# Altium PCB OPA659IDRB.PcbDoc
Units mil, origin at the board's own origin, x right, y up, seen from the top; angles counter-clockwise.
Board outline 4500 x 3000 mil, 4 copper layers (Top Layer, MidLayer1, MidLayer2, Bottom Layer); 16 components, 11 nets, 73 pads, 38 vias.
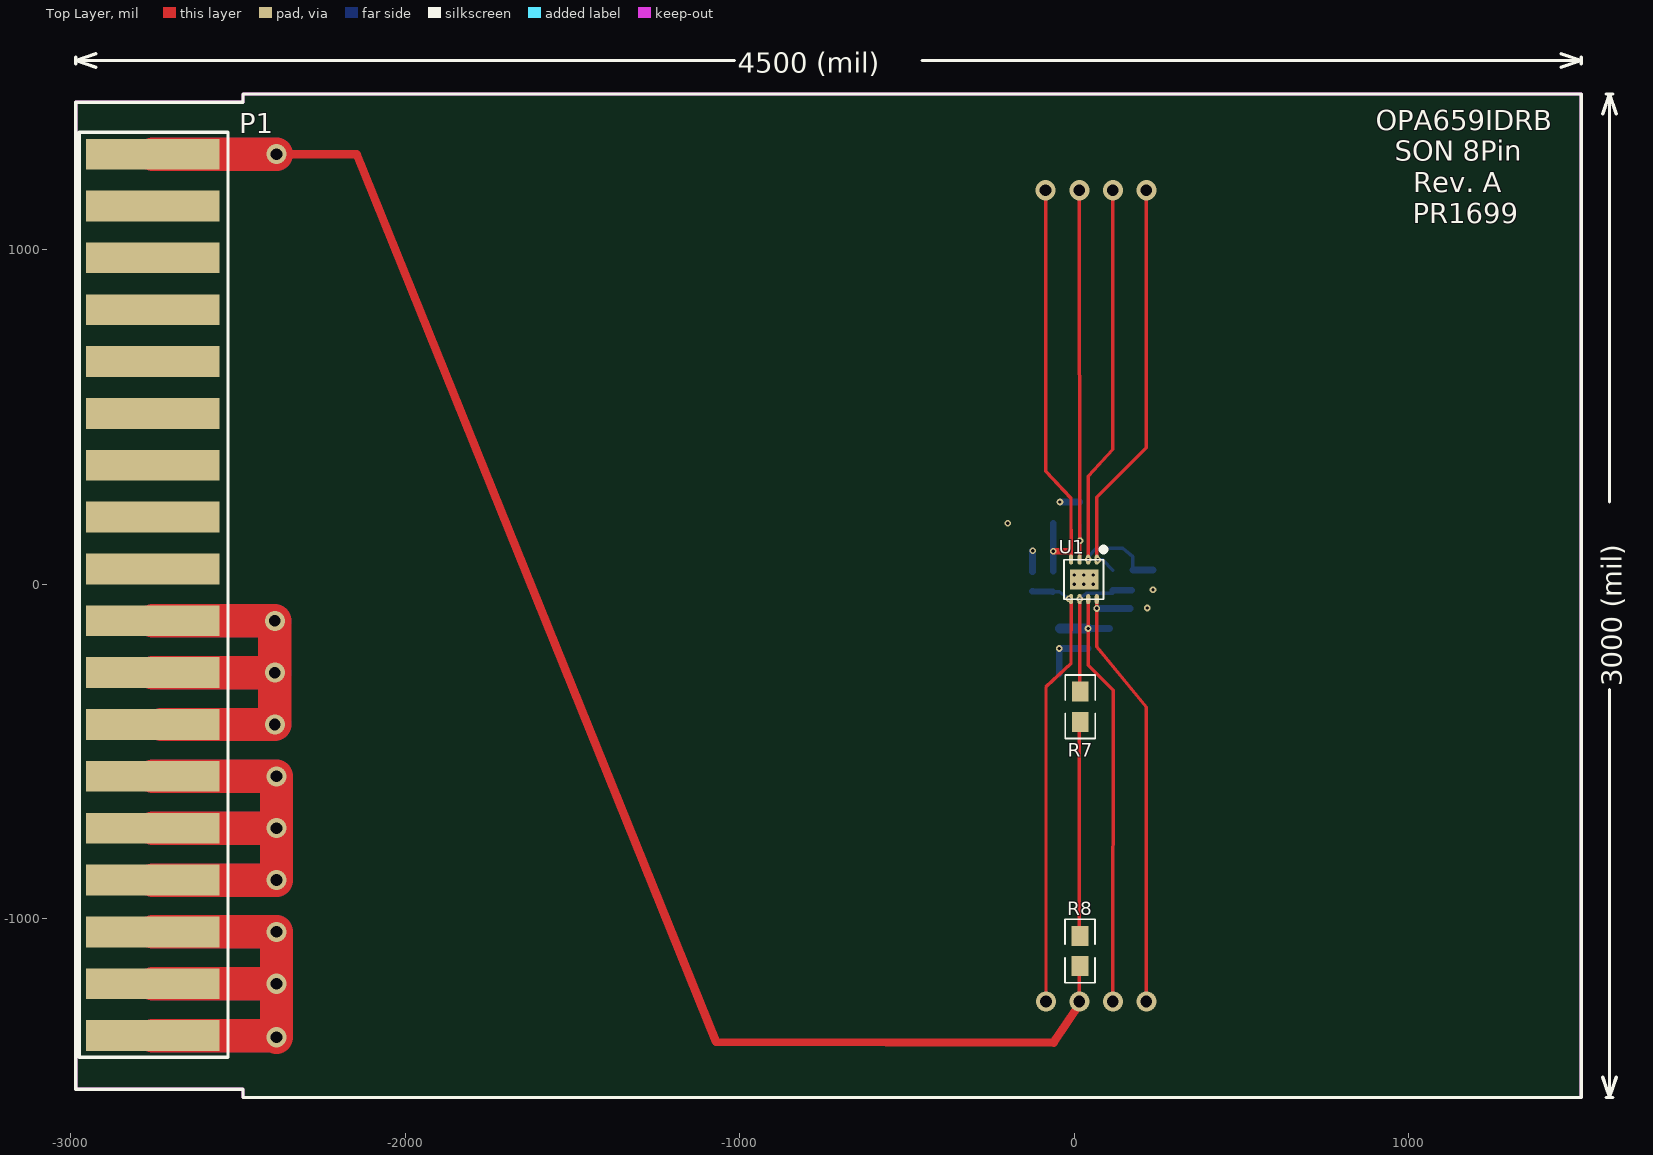
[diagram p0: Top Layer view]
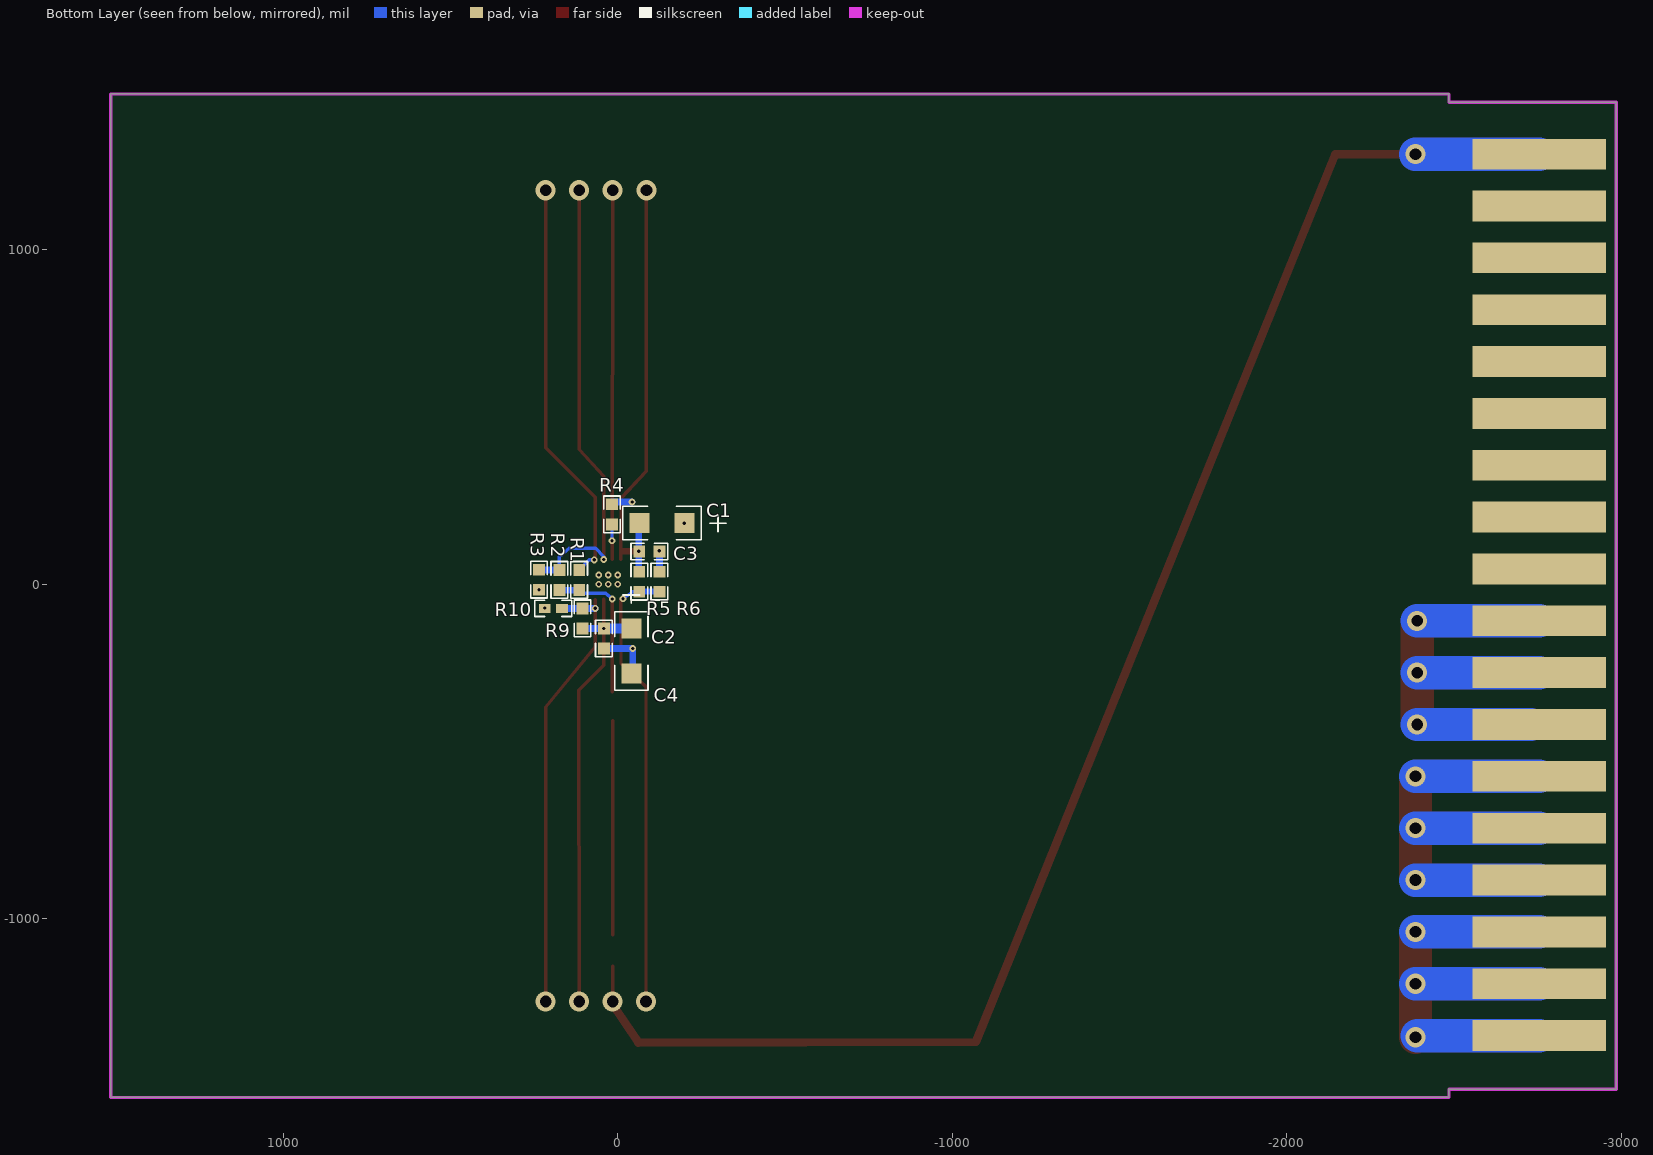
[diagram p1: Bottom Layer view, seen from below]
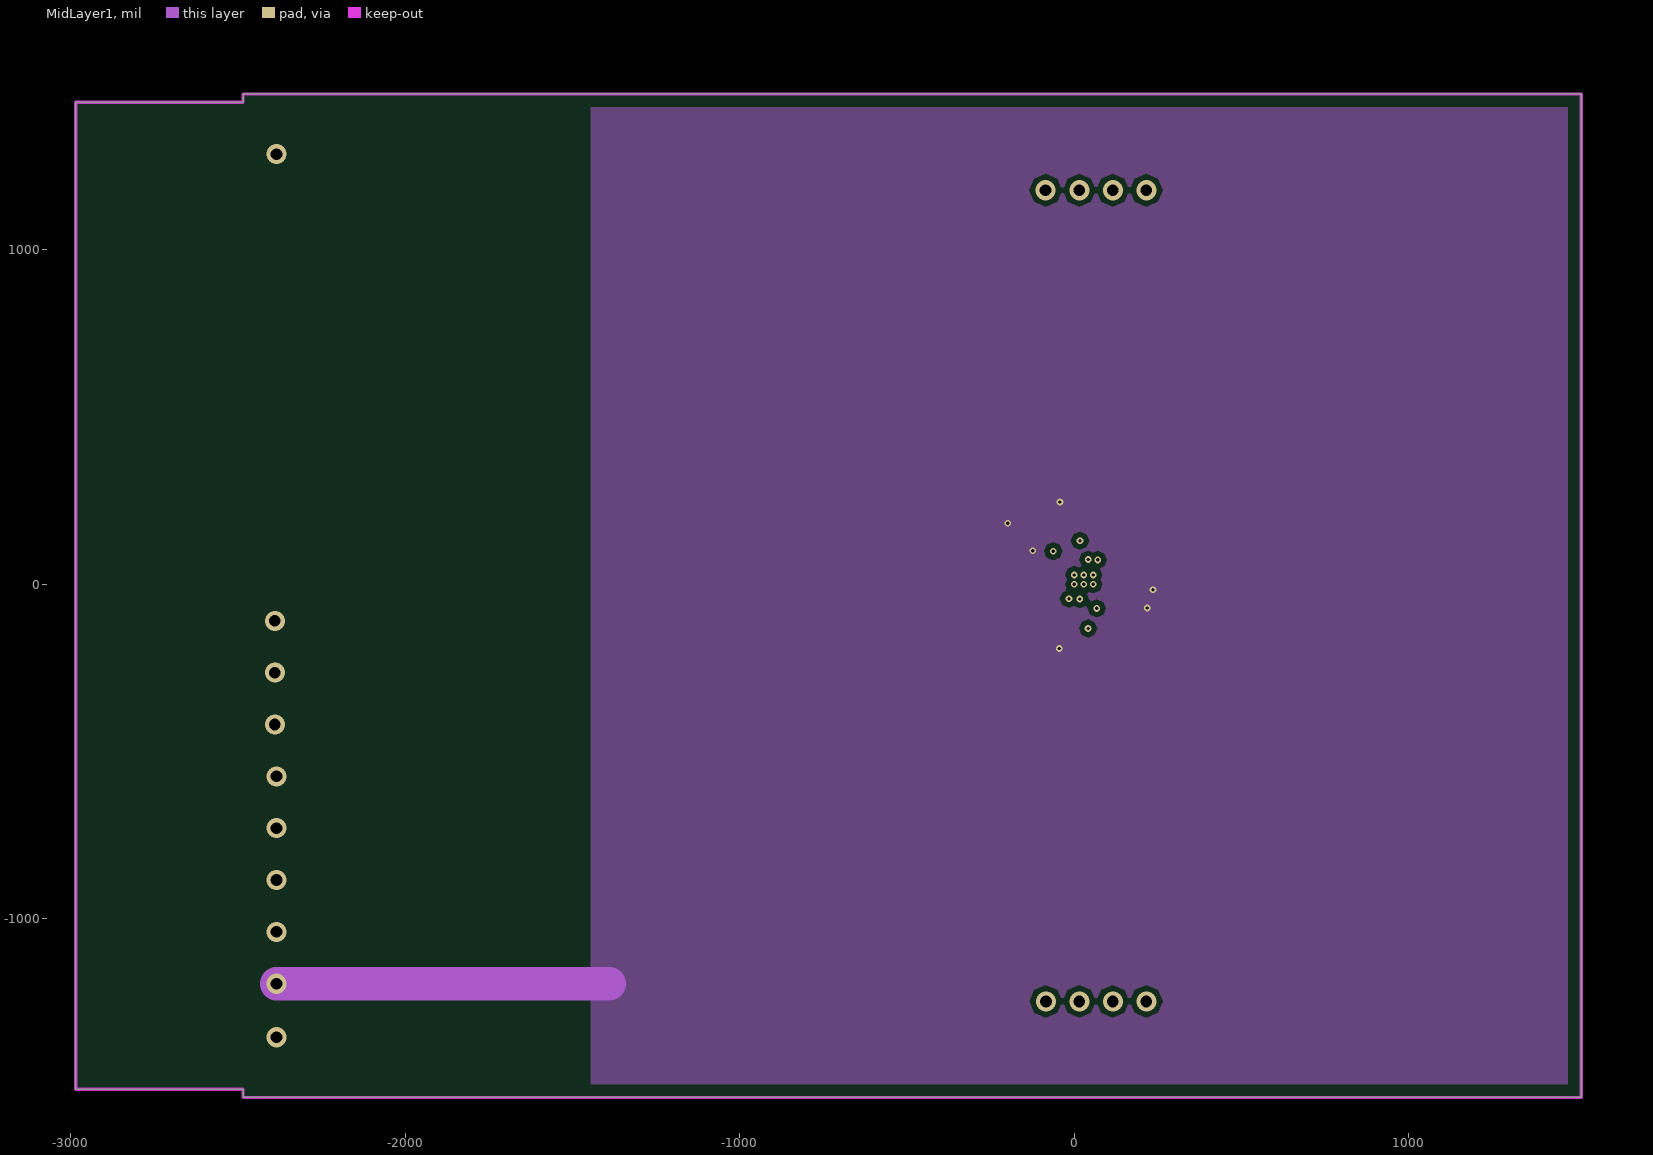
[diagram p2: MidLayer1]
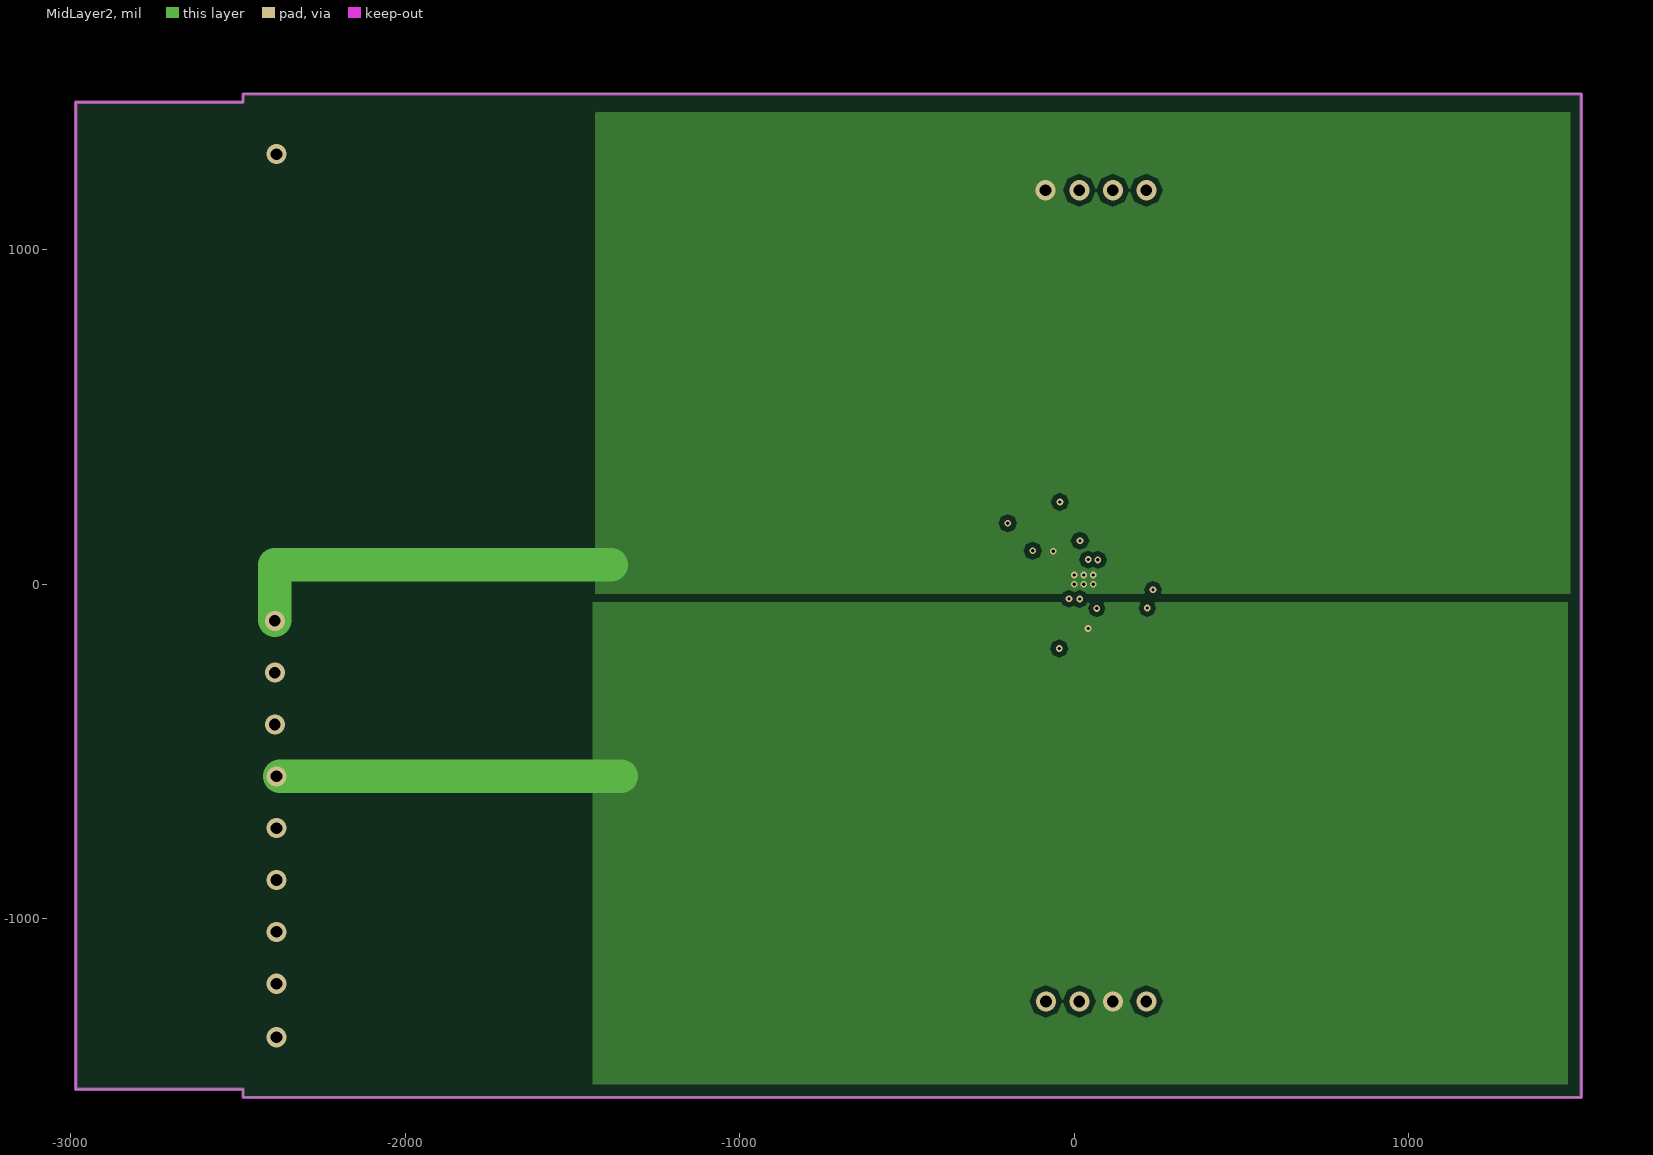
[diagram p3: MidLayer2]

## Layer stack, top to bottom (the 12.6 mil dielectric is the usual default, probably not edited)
Top Layer: signal copper 1.4
Dielectric: prepreg 12.6, FR-4, Dk 4.8
MidLayer1: signal copper 1.4
Dielectric: core 12.6, FR-4, Dk 4.8
MidLayer2: signal copper 1.4
Dielectric: prepreg 12.6, FR-4, Dk 4.8
Bottom Layer: signal copper 1.4

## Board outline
-2985.2,1441 -2485.2,1441 -2485.2,1466 1514.8,1466 1514.8,-1534 -2485.2,-1534 -2485.2,-1509 -2985.2,-1509

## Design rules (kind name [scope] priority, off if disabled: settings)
Clearance [All] p1: gap=5
ComponentClearance [All] p1: gap=10 collisioncheckmode=0 verticalgap=10
HoleSize [All] p1: absolutevalues=TRUE maxlimit=400 minlimit=0 maxpercent=80.000 minpercent=20.000
PlaneClearance [All] p1: clearance=30
PlaneConnect [All] p1: planeconnectstyle=Relief reliefexpansion=20 reliefentries=4 reliefconductorwidth=10 reliefairgap=15
PolygonConnect [All] p1: connectstyle=Relief reliefconductorwidth=25 reliefentries=4 polygonreliefangle="90 Angle"
RoutingLayers [All] p1: top layer_v5=TRUE mid layer 1_v5=FALSE mid layer 2_v5=FALSE bottom layer_v5=TRUE
RoutingVias [All] p1: holewidth=28 width=50 viastyle="Through Hole" minholewidth=28 minwidth=50 maxholewidth=28 maxwidth=50
ShortCircuit [All] p1 off: allowed=FALSE
SolderMaskExpansion [All] p1: expansion=4
TestPointUsage [All] p1: valid=0 allowmultiple=FALSE
Testpoint [All] p1: side=15 testpointundercomponent=TRUE minsize=40 maxsize=100 preferedsize=60 minholesize=0 maxholesize=40 preferedholesize=32 testpointgrid=1 style=1023 order=0123456789
Width [All] p1: maxlimit=1000 minlimit=10 preferedwidth=10 toplayer_prefwidth=20 bottomlayer_prefwidth=20 minimp=50.000000 maximp=50.000000 favimp=50.000000
12 further rules are at their usual default settings.

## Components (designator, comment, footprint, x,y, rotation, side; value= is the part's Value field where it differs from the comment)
C1 "10uF" "1206 (Pol)" -200.2,183 r0 bottom
C2 "0.1uF" 0603 41,-132 r270 bottom
C3 "0.1uF" 0603 -65,98 r180 bottom
C4 "10uF" "1206 (Pol)" -41,-132 r270 bottom
P1 "" DIP-40 -2755.2,1286 r0 top
R1 "499W" 0603 115,-17 r90 bottom (schematic designator R5)
R2 "499W" 0603 174,-17 r90 bottom (schematic designator R8)
R3 "499W" 0603 235,44 r270 bottom
R4 "49.9W" 0603 16.8,179 r90 bottom
R5 "49.9W" 0603 -65,-22 r90 bottom (schematic designator R7)
R6 "49.9W" 0603 -125,38 r270 bottom
R7 "1W" 0805 17.8,-411 r90 top
R8 "1W" 0805 16.8,-1141 r90 top
R9 "499W" 0603 105,-72 r270 bottom
R10 "49.9W" 0402 218,-72 r180 bottom
U1 "SON-08" "QFN 3x3 (8pin) DRB" 67,74 r180 top

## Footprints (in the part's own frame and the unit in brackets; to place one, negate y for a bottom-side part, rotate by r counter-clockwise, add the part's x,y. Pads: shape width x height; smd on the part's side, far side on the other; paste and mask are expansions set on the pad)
0402 [mm]
  rect 0.9x0.7 smd: 1(0,0) 2(1.3,0)
  silkscreen extent -0.76,-0.61 2.06,0.61
0603 [mil]
  rect 35x35 smd: 1(0,0) 2(60,0)
  silkscreen extent -25,-25 85,25
0805 [mil]
  rect 60x50 smd: 1(0,0) 2(90,0)
  silkscreen extent -50,-45 140,45
"1206 (Pol)" [mil]
  rect 60x60 smd: 1(0,0) 2(135,0)
  silkscreen extent -125,-50 185,50
DIP-40 [mil]
  rect 400x92 smd: 1(0,0) 2(0,-155) 3(0,-310) 4(0,-465) 5(0,-620) 6(0,-775) 7(0,-930) 8(0,-1085) 9(0,-1240) 10(0,-1395) 11(0,-1550) 12(0,-1705) 13(0,-1860) 14(0,-2015) 15(0,-2170) 16(0,-2325) 17(0,-2480) 18(0,-2635)
  rect 400x92 smd far side: 19(0,0) 20(0,-155) 21(0,-310) 22(0,-465) 23(0,-620) 24(0,-775) 25(0,-930) 26(0,-1085) 27(0,-1240) 28(0,-1395) 29(0,-1550) 30(0,-1705) 31(0,-1860) 32(0,-2015) 33(0,-2170) 34(0,-2325) 35(0,-2480) 36(0,-2635)
  silkscreen extent -220,-2700 225,65
"QFN 3x3 (8pin) DRB" [mil] "3x3mm SON 8 lead"
  oval 12.2x30 smd: 1(0,0) 2(25.6,0) 3(51.2,0) 4(76.8,0) 5(76.8,118) 6(51.2,118) 7(25.6,118) 8(0,118)
  rect 85x60 smd: 9(38,59.5)
  silkscreen extent -20,-30 98,119

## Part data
C1 C4: library part "CAP (Polarized SM)"
C2 C3: library part CAP
R1 R2 R5 R6 R7 R9 R10: library part "RES (SM)"
U1: library part MSOP-08

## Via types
v1: diameter 60, hole 35, Top Layer to Bottom Layer, 18 vias
v2: diameter 20, hole 10, Top Layer to Bottom Layer, 14 vias
v3: diameter 20, hole 10, Top Layer to Bottom Layer, tented top, 6 vias

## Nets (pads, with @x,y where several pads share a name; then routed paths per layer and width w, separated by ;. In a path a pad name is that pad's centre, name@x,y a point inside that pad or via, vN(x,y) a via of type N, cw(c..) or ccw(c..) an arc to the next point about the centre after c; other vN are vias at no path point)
GND: C1.1 C2.2 C3.2 C4.2 P1.16 P1.17 P1.18 P1.34 P1.35 P1.36 R3.2 R4.2 R6.1 R10.1 | length 3802
  Top Layer w100: P1.18 v1@-2390.2,-1349 ; P1.17 v1(-2385.2,-1194) ; P1.16 v1(-2385.2,-1039) v1(-2385.2,-1194) ; v1(-2385.2,-1354) v1(-2385.2,-1194)
  MidLayer1 w100: v1(-2385.2,-1194) -1390.2,-1194
  Bottom Layer w20: R6.1 C3.2@-125,100 ; C4.2@-45,-268 v2@-45,-193 ; v2(-45,-192) C2.2 ; v2(-43.2,246) R4.2@15.8,246
  Bottom Layer w100: P1.36 v1@-2390.2,-1349 ; P1.35 v1(-2385.2,-1194) ; P1.34 v1(-2385.2,-1039)
  other v2: 218,-71 235,-16 -124.2,100 -199.2,183
NetC1_2: C1.2 C3.1 P1.10 P1.11 P1.12 P1.28 P1.29 P1.30 R5.2 U1.4 U1.9 | length 4944.7
  Top Layer w10: v1(-86,1178) -86,338 -10,258 U1.4
  Top Layer w20: v2(-63.2,99) -15,99
  Top Layer w100: P1.11 v1(-2390.2,-264) ; P1.10 v1(-2390.2,-109) v1(-2390.2,-264) ; P1.12@-2730.2,-419 v1(-2390.2,-419) v1(-2390.2,-264)
  MidLayer2 w100: v1@-2390.2,-108 -2390.2,56 ; -2390.2,58 -1385,59
  Bottom Layer w20: R5.2@-63.2,39 v2(-63.2,99) C1.2@-63.2,182
  Bottom Layer w100: P1.29 v1(-2390.2,-264) ; P1.28 v1(-2390.2,-109) ; P1.30@-2730.2,-419 v1(-2390.2,-419)
  other v3: 0,0 28,0 56,0 0,28 28,28 56,28
NetC2_1: C2.1 C4.1 P1.13 P1.14 P1.15 P1.31 P1.32 P1.33 R9.2 U1.7 | length 4931.9
  Top Layer w10: U1.7@41,-44 41,-242 115.8,-317 v1(115,-1247)
  Top Layer w100: P1.15 v1(-2385.2,-884) v1(-2385.2,-729) ; P1.14 v1(-2385.2,-729) ; P1.13 v1(-2385.2,-574) v1(-2385.2,-729)
  MidLayer2 w100: v1@-2375.2,-574 -1355.2,-574
  Bottom Layer w20: v2(41,-132) R9.2
  Bottom Layer w30: C4.1@-43,-132 v2(41,-132)
  Bottom Layer w100: P1.33 v1(-2385.2,-884) ; P1.32 v1(-2385.2,-729) ; P1.31 v1(-2385.2,-574)
NetP1_1: P1.1 P1.19 R8.1 | length 5101.7
  Top Layer w10: v1@15,-1248 R8.1@15,-1142
  Top Layer w25: v1(-2385.2,1286) -2145,1286 -1071.2,-1368 -62,-1370 v1@17.8,-1251
  Top Layer w100: P1.1 v1(-2385.2,1286)
  Bottom Layer w100: P1.19 v1(-2385.2,1286)
  other v1: 15,-1247
NetR1_1: R1.1 R2.1 R7.2 U1.6 | length 439.6
  Top Layer w10: v2(15.8,-44) R7.2@16,-321
  Bottom Layer w10: v2(15.8,-44) 35,-27 R1.1@115,-27
  Bottom Layer w20: R1.1@114.8,-18 R2.1@171.8,-18
NetR1_2: R1.2 U1.1 | length 1226.9
  Top Layer w10: U1.1@67,73 66.8,261 215,408 v1@215,1180
  Bottom Layer w10: v2(70,73) 85,73 R1.2@115,42
  other v1: 215,1178
NetR2_2: R2.2 R3.1 U1.2 | length 1395.4
  Top Layer w10: v2(41.4,74) 41,323 115,403 v1(115,1178)
  Bottom Layer w10: v2(41.4,74) 41,83 66,108 145,108 175,83 R2.2@175,43
  Bottom Layer w20: R2.2@175,43 R3.1@235,43
NetR4_1: R4.1 U1.3 | length 1153
  Top Layer w10: v1(15,1178) U1.3
  Bottom Layer w10: v2(16.8,130) R4.1
NetR5_1: R5.1 R6.2 U1.5 | length 1352.1
  Top Layer w10: v1(-85,-1247) -85,-307 -10,-236 U1.5@-9.8,-43
  Bottom Layer w10: R5.1 -45,-22 v2(-16,-43)
  Bottom Layer w20: R6.2@-125,-21 R5.1
NetR7_1: R7.1 R8.2 | length 641
  Top Layer w10: R8.2@15,-1048 R7.1@15,-407
NetR9_1: R9.1 R10.2 U1.8 | length 1353.9
  Top Layer w10: U1.8@67,-46 67,-187 215,-367 v1(215,-1247)
  Bottom Layer w20: v2(67,-72) R10.2
pads on no net: P1.2 P1.3 P1.4 P1.5 P1.6 P1.7 P1.8 P1.9 P1.20 P1.21 P1.22 P1.23 P1.24 P1.25 P1.26 P1.27

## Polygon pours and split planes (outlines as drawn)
GND on MidLayer1 (solid, remove dead copper): 1474.8,1426 1474.8,-1494 -1445.2,-1494 -1445.2,1426 1474.8,1426
NetC1_2 on MidLayer2 (solid, remove dead copper): -1432.03,1412.48 -1432.03,-27.52 1482.97,-27.52 1482.97,1411.48
NetC2_1 on MidLayer2 (solid, remove dead copper): 1474.8,-1494 1474.8,-54 -1440.2,-54 -1440.2,-1494

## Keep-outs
Keep-Out Layer:
  lines w10: 1514.8,-1524 1514.8,1466 ; -2485.2,-1534 1514.8,-1534 ; -2485.2,-1534 1514.8,-1534 ; -2485.2,-1534 -2485.2,-1509 -2985.2,-1509 -2985.2,1441 -2735.2,1441 -2485.2,1441 -2485.2,1451 -2485.2,1466 1514.8,1466 ; 1514.8,-1534 1514.8,1466

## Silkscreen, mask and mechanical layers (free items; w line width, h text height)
Top Overlay:
  lines w10: -2985.2,1556 -2985.2,1576 ; -2925.2,1546 -2985.2,1566 ; -2925.2,1586 -2985.2,1566 ; -1016.11,1566 -2985.2,1566 ; -454.29,1566 1514.8,1566 ; 1454.8,1546 1514.8,1566 ; 1454.8,1586 1514.8,1566 ; 1514.8,1556 1514.8,1576 ; 1579.8,-1474 1599.8,-1534 ; 1579.8,1406 1599.8,1466 ; 1589.8,-1534 1609.8,-1534 ; 1589.8,1466 1609.8,1466 ; 1599.8,-314.91 1599.8,-1534 ; 1599.8,246.91 1599.8,1466 ; 1619.8,-1474 1599.8,-1534 ; 1619.8,1406 1599.8,1466 ; -2985.2,-1509 -2485.2,-1509 -2485.2,-1534 1514.8,-1534 1514.8,1466 -2485.2,1466 -2485.2,1441 -2985.2,1441 -2985.2,-1509
  text "4500 (mil)" at -1006.11,1530.01 h60
  text "OPA659IDRB" at 900.8,1357 h60
  text "SON 8Pin" at 957.8,1266 h60
  text "Rev. A" at 1013.8,1172 h60
  text "PR1699" at 1011.8,1079 h60
  text "3000 (mil)" at 1635.79,-304.91 h60 r90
